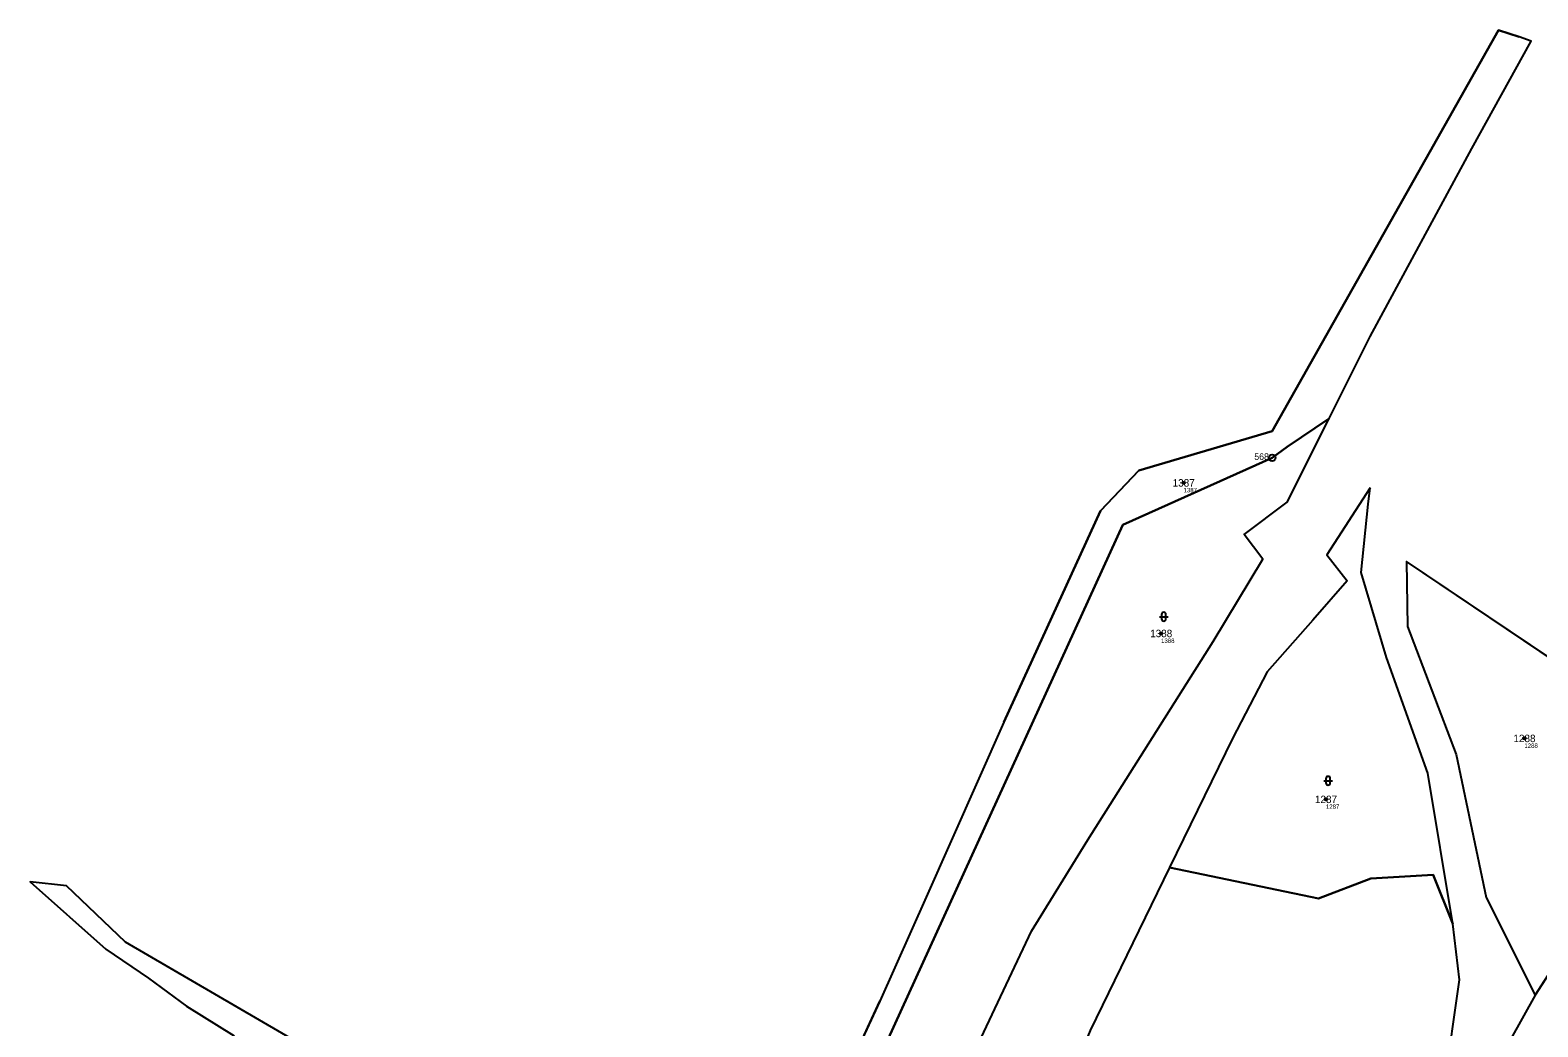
# Model space of a CAD drawing. Extents: x -781091 to -780384, y -1093010 to -1092030.
# Drawn here: x -780935.3 to -780590.6, y -1092257.6 to -1092029.8 of the extents above; entities that cross this region are included whole.
import ezdxf

# ---------------------------------------------------------------- set-up
doc = ezdxf.new("R2010")
doc.units = 0
for name, color, linetype in [('Vrstva 1', 7, 'Continuous'), ('Vrstva 2', 7, 'Continuous'), ('Vrstva 3', 7, 'Continuous'), ('Vrstva 50', 7, 'Continuous'), ('Vrstva 51', 7, 'Continuous'), ('Vrstva 8', 7, 'Continuous')]:
    doc.layers.add(name, color=color, linetype=linetype)

msp = doc.modelspace()

# ---------------------------------------------------------------- linework, layer by layer
at = {"layer": 'Vrstva 1'}
for p, q in [((-780599.65, -1092029.77), (-780594.95, -1092031.33)), ((-780592.19, -1092032.25), (-780594.95, -1092031.33)), ((-780555.61, -1092195), (-780620.64, -1092151.21)), ((-780712.7, -1092187.91), (-780730.47, -1092227.91)), ((-780555.61, -1092195), (-780591.27, -1092250.31)), ((-780730.47, -1092227.91), (-780741.07, -1092251.75)), ((-780750.09, -1092271.06), (-780741.07, -1092251.75))]:
    msp.add_line(p, q, dxfattribs=at)
for points in [[(-780712.7, -1092187.91), (-780690.61, -1092139.65), (-780681.84, -1092130.42), (-780651.37, -1092121.46), (-780599.65, -1092029.77)], [(-780638.36, -1092118.5), (-780629, -1092099.77), (-780605.74, -1092056.81), (-780592.19, -1092032.25)], [(-780747.21, -1092277.83), (-780685.55, -1092142.84), (-780651.37, -1092127.5), (-780647.92, -1092125.01), (-780638.36, -1092118.5)], [(-780728.65, -1092285.26), (-780727.61, -1092280.58), (-780706.42, -1092235.73), (-780693.52, -1092214.87), (-780664.87, -1092169.47), (-780653.5, -1092150.68), (-780657.75, -1092145.05), (-780647.94, -1092137.67), (-780638.36, -1092118.5)], [(-780628.96, -1092134.39), (-780638.91, -1092149.72), (-780634.21, -1092155.61), (-780642.05, -1092164.61), (-780652.51, -1092176.42), (-780660.49, -1092191.68), (-780674.85, -1092221.17)], [(-780610.07, -1092234.05), (-780615.79, -1092199.59), (-780625.28, -1092173.17), (-780631.02, -1092153.7), (-780629.4, -1092138.1), (-780628.96, -1092134.39)], [(-780620.64, -1092151.21), (-780620.46, -1092166.09), (-780609.32, -1092195.36), (-780602.47, -1092228.03), (-780591.27, -1092250.31)], [(-780674.85, -1092221.17), (-780693, -1092258.45), (-780698.75, -1092272.47), (-780706.06, -1092290.15)], [(-780610.07, -1092234.05), (-780614.6, -1092222.86), (-780628.85, -1092223.69), (-780640.82, -1092228.27), (-780674.85, -1092221.17)], [(-780622.45, -1092295.31), (-780612, -1092270.91), (-780608.54, -1092246.82), (-780610.07, -1092234.05)], [(-780591.27, -1092250.31), (-780604.95, -1092274.93), (-780616.5, -1092294.82)]]:
    msp.add_lwpolyline(points, dxfattribs=at)
at = {"layer": 'Vrstva 3'}
for p, q in [((-780676.681, -1092163.331), (-780676.681, -1092164.332)), ((-780675.679, -1092164.332), (-780675.679, -1092163.331)), ((-780677.181, -1092163.831), (-780675.179, -1092163.831)), ((-780639.591, -1092201.331), (-780637.589, -1092201.331)), ((-780639.091, -1092200.831), (-780639.091, -1092201.832)), ((-780638.089, -1092201.832), (-780638.089, -1092200.831))]:
    msp.add_line(p, q, dxfattribs=at)
for centre, start, end in [((-780676.18, -1092163.3309), 0, 180), ((-780676.18, -1092164.3309), 180, 359.9878861), ((-780638.59, -1092200.8309), 0, 180), ((-780638.59, -1092201.8309), 180, 359.9878861)]:
    msp.add_arc(centre, 0.5, start, end, dxfattribs=at)
at = {"layer": 'Vrstva 50'}
for centre in [(-780671.64, -1092133.24994), (-780676.78, -1092167.66994), (-780593.72, -1092191.65994), (-780639.1, -1092205.58994)]:
    msp.add_circle(centre, 0.25, dxfattribs=at)
at = {"layer": 'Vrstva 51'}
for points in [[(-780730.47, -1092227.91), (-780741.07, -1092251.75), (-780750.09, -1092271.06), (-780752.3, -1092275.79), (-780747.21, -1092277.83), (-780685.55, -1092142.84), (-780651.37, -1092127.5), (-780647.92, -1092125.01), (-780638.36, -1092118.5), (-780629, -1092099.77), (-780605.74, -1092056.81), (-780592.19, -1092032.25), (-780594.95, -1092031.33), (-780599.65, -1092029.77), (-780651.37, -1092121.46), (-780681.84, -1092130.42), (-780690.61, -1092139.65), (-780712.7, -1092187.91)], [(-780706.42, -1092235.73), (-780693.52, -1092214.87), (-780664.87, -1092169.47), (-780653.5, -1092150.68), (-780657.75, -1092145.05), (-780647.94, -1092137.67), (-780638.36, -1092118.5), (-780647.92, -1092125.01), (-780651.37, -1092127.5), (-780685.55, -1092142.84), (-780747.21, -1092277.83), (-780728.65, -1092285.26), (-780727.61, -1092280.58)], [(-780628.96, -1092134.39), (-780638.91, -1092149.72), (-780634.21, -1092155.61), (-780642.05, -1092164.61), (-780652.51, -1092176.42), (-780660.49, -1092191.68), (-780674.85, -1092221.17), (-780640.82, -1092228.27), (-780628.85, -1092223.69), (-780614.6, -1092222.86), (-780610.07, -1092234.05), (-780615.79, -1092199.59), (-780625.28, -1092173.17), (-780631.02, -1092153.7), (-780629.4, -1092138.1)], [(-780609.32, -1092195.36), (-780602.47, -1092228.03), (-780591.27, -1092250.31), (-780555.61, -1092195), (-780620.64, -1092151.21), (-780620.46, -1092166.09)], [(-780614.6, -1092222.86), (-780628.85, -1092223.69), (-780640.82, -1092228.27), (-780674.85, -1092221.17), (-780693, -1092258.45), (-780698.75, -1092272.47), (-780706.06, -1092290.15), (-780686.44, -1092304.47), (-780668.03, -1092327.21), (-780645.88, -1092310.74), (-780640.77, -1092302.69), (-780622.45, -1092295.31), (-780612, -1092270.91), (-780608.54, -1092246.82), (-780610.07, -1092234.05)]]:
    msp.add_lwpolyline(points, close=True, dxfattribs=at)
msp.add_lwpolyline([(-780867.63, -1092264.99), (-780913.54, -1092238.2), (-780927.06, -1092225.33), (-780935.35, -1092224.47), (-780918.02, -1092239.83), (-780908.3, -1092246.47), (-780899.58, -1092252.88), (-780888.73, -1092259.62)], dxfattribs=at)
at = {"layer": 'Vrstva 8'}
for radius in [0.75, 0.03]:
    msp.add_circle((-780651.37, -1092127.49982), radius, dxfattribs=at)

# ---------------------------------------------------------------- texts
at = {"layer": 'Vrstva 2'}
for s, p in [('1387', (-780674.147, -1092134.1)), ('1388', (-780679.287, -1092168.52)), ('1288', (-780596.227, -1092192.51)), ('1287', (-780641.607, -1092206.44))]:
    msp.add_text(s, height=1.699998, dxfattribs=at).set_placement(p)
at = {"layer": 'Vrstva 50'}
for s, p in [('1387', (-780671.64, -1092135.406)), ('1388', (-780676.78, -1092169.826)), ('1288', (-780593.72, -1092193.816)), ('1287', (-780639.1, -1092207.746))]:
    msp.add_text(s, height=0.999996, dxfattribs=at).set_placement(p)
at = {"layer": 'Vrstva 8'}
msp.add_text('568', height=1.499994, dxfattribs=at).set_placement((-780655.473, -1092128))

doc.saveas('drawing.dxf')
